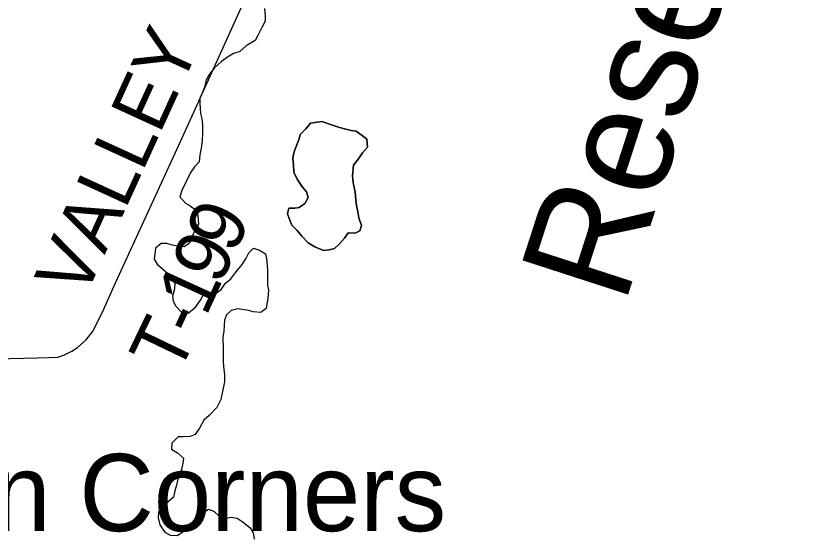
# Model space of a CAD drawing. Extents: x -10.1 to 68, y -9.5 to 29.2.
# Drawn here: x 5.518 to 6.333, y 19.418 to 19.95 of the extents above; entities that cross this region are included whole.
import ezdxf

# ---------------------------------------------------------------- set-up
doc = ezdxf.new("R2010")
doc.units = 0
for name, color, linetype in [('GM_X_Major_Lake', 7, 'Continuous'), ('GM_X_Major_Lake_Text', 7, 'Continuous'), ('GM_X_Major_River', 7, 'Continuous'), ('GM_X_Township_Road', 7, 'Continuous'), ('GM_X_Township_Road_Text', 7, 'Continuous'), ('GM_X_Unincorporated_Text', 7, 'Continuous')]:
    doc.layers.add(name, color=color, linetype=linetype)

msp = doc.modelspace()

# ---------------------------------------------------------------- linework, layer by layer
at = {"layer": 'GM_X_Major_Lake'}
for points in [[(5.77192, 19.95774), (5.77267, 19.94976), (5.77267, 19.94482), (5.76926, 19.93836), (5.76508, 19.93), (5.76242, 19.92505), (5.75331, 19.91935), (5.74686, 19.91364), (5.74041, 19.91173), (5.73434, 19.90793), (5.72789, 19.90336), (5.72068, 19.89652), (5.71574, 19.89043), (5.71233, 19.88473), (5.71081, 19.87827), (5.70853, 19.87181), (5.70588, 19.86611), (5.70588, 19.86041), (5.70663, 19.85015), (5.70777, 19.84484), (5.70852, 19.83838), (5.70852, 19.8304), (5.70814, 19.82242), (5.70738, 19.81483), (5.70586, 19.80799), (5.7051, 19.80077), (5.70055, 19.79583), (5.69599, 19.78936), (5.6922, 19.78138), (5.68726, 19.7715), (5.68536, 19.76504), (5.69105, 19.75858), (5.69598, 19.75593), (5.70092, 19.75214), (5.70395, 19.74606), (5.70432, 19.73695), (5.70091, 19.73124), (5.69863, 19.7263), (5.69521, 19.71756), (5.6899, 19.71376), (5.68459, 19.71413), (5.67776, 19.71564), (5.67207, 19.71715), (5.66638, 19.71715), (5.66031, 19.71258), (5.65917, 19.70119), (5.6622, 19.69625), (5.66751, 19.69132), (5.6732, 19.68676), (5.67813, 19.68145), (5.68041, 19.67652), (5.68003, 19.67082), (5.67775, 19.6636), (5.67851, 19.65828), (5.68116, 19.65334), (5.68685, 19.64727), (5.69406, 19.64614), (5.70165, 19.65261), (5.70734, 19.66021), (5.71114, 19.66819), (5.71645, 19.66744), (5.7229, 19.66669), (5.72783, 19.67011), (5.73201, 19.67658), (5.7377, 19.68114), (5.74263, 19.68799), (5.74909, 19.69597), (5.75288, 19.70167), (5.75592, 19.70776), (5.76085, 19.7127), (5.76692, 19.71043), (5.77299, 19.70663), (5.77413, 19.7017), (5.77489, 19.69524), (5.77526, 19.68954), (5.77526, 19.67473), (5.77602, 19.66979), (5.77564, 19.66067), (5.7745, 19.65573), (5.77374, 19.65079), (5.76842, 19.64661), (5.76046, 19.64736), (5.75552, 19.64887), (5.7449, 19.65038), (5.73807, 19.64885), (5.73314, 19.64429), (5.73124, 19.63897), (5.73086, 19.63327), (5.73048, 19.62719), (5.72934, 19.62225), (5.72971, 19.60933), (5.72971, 19.5968), (5.73009, 19.59148), (5.73123, 19.58312), (5.73122, 19.57591), (5.72895, 19.56603), (5.72743, 19.55767), (5.72325, 19.54969), (5.71528, 19.54132), (5.70997, 19.53676), (5.70541, 19.52839)], [(5.79691, 19.75339), (5.79577, 19.74769), (5.79728, 19.74275), (5.79994, 19.73592), (5.80563, 19.73061), (5.81018, 19.72491), (5.81663, 19.71808), (5.82345, 19.71391), (5.83256, 19.71012), (5.83825, 19.71089), (5.84356, 19.71204), (5.8485, 19.7166), (5.85381, 19.72269), (5.85761, 19.72839), (5.86481, 19.72801), (5.86975, 19.7303), (5.87127, 19.73562), (5.86861, 19.7436), (5.86748, 19.74967), (5.86634, 19.75613), (5.86558, 19.76183), (5.86482, 19.7698), (5.86293, 19.77968), (5.86217, 19.78651), (5.86331, 19.79753), (5.86825, 19.804), (5.87242, 19.81008), (5.87736, 19.81578), (5.87698, 19.82414), (5.87205, 19.82793), (5.86598, 19.83211), (5.86067, 19.83286), (5.85536, 19.83437), (5.84891, 19.83588), (5.84359, 19.83778), (5.83752, 19.83967), (5.83108, 19.84194), (5.82614, 19.84156), (5.81931, 19.84041), (5.81438, 19.8347), (5.80907, 19.829), (5.80679, 19.82254), (5.80375, 19.81494), (5.80223, 19.81), (5.80109, 19.8043), (5.80185, 19.79784), (5.80223, 19.79024), (5.80564, 19.78303), (5.81095, 19.77506), (5.81512, 19.77012), (5.81664, 19.76443), (5.81322, 19.75835), (5.80753, 19.75416), (5.80298, 19.7534)], [(5.80298, 19.7534), (5.79691, 19.75339)], [(5.70541, 19.52839), (5.70124, 19.52193), (5.69592, 19.52002), (5.68872, 19.51964), (5.68378, 19.51963), (5.67733, 19.51316), (5.67695, 19.50708), (5.68302, 19.50329), (5.68909, 19.4976), (5.68833, 19.49266), (5.68719, 19.4862), (5.68415, 19.47974), (5.68187, 19.47024), (5.68035, 19.46416), (5.67884, 19.4577), (5.67352, 19.45314), (5.66707, 19.44743), (5.66366, 19.44249), (5.66327, 19.43679), (5.66479, 19.42958), (5.6701, 19.42198), (5.67541, 19.41895), (5.68262, 19.41858), (5.69059, 19.42391), (5.69932, 19.43265), (5.70577, 19.4376), (5.70994, 19.44254), (5.71488, 19.44559), (5.72057, 19.44332), (5.7255, 19.43838), (5.73157, 19.43611), (5.73802, 19.43726), (5.74409, 19.4365), (5.75016, 19.43233), (5.75737, 19.42664), (5.7604, 19.42133), (5.76154, 19.41487)]]:
    msp.add_lwpolyline(points, dxfattribs=at)
at = {"layer": 'GM_X_Major_River'}
for points in [[(5.77192, 19.95774), (5.77267, 19.94976), (5.77267, 19.94482), (5.76926, 19.93836), (5.76508, 19.93), (5.76242, 19.92505), (5.75331, 19.91935), (5.74686, 19.91364), (5.74041, 19.91173), (5.73434, 19.90793), (5.72789, 19.90336), (5.72068, 19.89652), (5.71574, 19.89043), (5.71233, 19.88473), (5.71081, 19.87827), (5.70853, 19.87181), (5.70588, 19.86611), (5.70588, 19.86041), (5.70663, 19.85015), (5.70777, 19.84484), (5.70852, 19.83838), (5.70852, 19.8304), (5.70814, 19.82242), (5.70738, 19.81483), (5.70586, 19.80799), (5.7051, 19.80077), (5.70055, 19.79583), (5.69599, 19.78936), (5.6922, 19.78138), (5.68726, 19.7715), (5.68536, 19.76504), (5.69105, 19.75858), (5.69598, 19.75593), (5.70092, 19.75214), (5.70395, 19.74606), (5.70432, 19.73695), (5.70091, 19.73124), (5.69863, 19.7263), (5.69521, 19.71756), (5.6899, 19.71376), (5.68459, 19.71413), (5.67776, 19.71564), (5.67207, 19.71715), (5.66638, 19.71715), (5.66031, 19.71258), (5.65917, 19.70119), (5.6622, 19.69625), (5.66751, 19.69132), (5.6732, 19.68676), (5.67813, 19.68145), (5.68041, 19.67652), (5.68003, 19.67082), (5.67775, 19.6636), (5.67851, 19.65828), (5.68116, 19.65334), (5.68685, 19.64727), (5.69406, 19.64614), (5.70165, 19.65261), (5.70734, 19.66021), (5.71114, 19.66819), (5.71645, 19.66744), (5.7229, 19.66669), (5.72783, 19.67011), (5.73201, 19.67658), (5.7377, 19.68114), (5.74263, 19.68799), (5.74909, 19.69597), (5.75288, 19.70167), (5.75592, 19.70776), (5.76085, 19.7127), (5.76692, 19.71043), (5.77299, 19.70663), (5.77413, 19.7017), (5.77489, 19.69524), (5.77526, 19.68954), (5.77526, 19.67473), (5.77602, 19.66979), (5.77564, 19.66067), (5.7745, 19.65573), (5.77374, 19.65079), (5.76842, 19.64661), (5.76046, 19.64736), (5.75552, 19.64887), (5.7449, 19.65038), (5.73807, 19.64885), (5.73314, 19.64429), (5.73124, 19.63897), (5.73086, 19.63327), (5.73048, 19.62719), (5.72934, 19.62225), (5.72971, 19.60933), (5.72971, 19.5968), (5.73009, 19.59148), (5.73123, 19.58312), (5.73122, 19.57591), (5.72895, 19.56603), (5.72743, 19.55767), (5.72325, 19.54969), (5.71528, 19.54132), (5.70997, 19.53676), (5.70541, 19.52839)], [(5.80298, 19.7534), (5.80753, 19.75416), (5.81322, 19.75835), (5.81664, 19.76443), (5.81512, 19.77012), (5.81095, 19.77506), (5.80564, 19.78303), (5.80223, 19.79024), (5.80185, 19.79784), (5.80109, 19.8043), (5.80223, 19.81), (5.80375, 19.81494), (5.80679, 19.82254), (5.80907, 19.829), (5.81438, 19.8347), (5.81931, 19.84041), (5.82614, 19.84156), (5.83108, 19.84194), (5.83752, 19.83967), (5.84359, 19.83778), (5.84891, 19.83588), (5.85536, 19.83437), (5.86067, 19.83286), (5.86598, 19.83211), (5.87205, 19.82793), (5.87698, 19.82414), (5.87736, 19.81578), (5.87242, 19.81008), (5.86825, 19.804), (5.86331, 19.79753), (5.86217, 19.78651), (5.86293, 19.77968), (5.86482, 19.7698), (5.86558, 19.76183), (5.86634, 19.75613), (5.86748, 19.74967), (5.86861, 19.7436), (5.87127, 19.73562), (5.86975, 19.7303), (5.86481, 19.72801), (5.85761, 19.72839), (5.85381, 19.72269), (5.8485, 19.7166), (5.84356, 19.71204), (5.83825, 19.71089), (5.83256, 19.71012), (5.82345, 19.71391), (5.81663, 19.71808), (5.81018, 19.72491), (5.80563, 19.73061), (5.79994, 19.73592), (5.79728, 19.74275), (5.79577, 19.74769), (5.79691, 19.75339)], [(5.79691, 19.75339), (5.80298, 19.7534)], [(5.70541, 19.52839), (5.70124, 19.52193), (5.69592, 19.52002), (5.68872, 19.51964), (5.68378, 19.51963), (5.67733, 19.51316), (5.67695, 19.50708), (5.68302, 19.50329), (5.68909, 19.4976), (5.68833, 19.49266), (5.68719, 19.4862), (5.68415, 19.47974), (5.68187, 19.47024), (5.68035, 19.46416), (5.67884, 19.4577), (5.67352, 19.45314), (5.66707, 19.44743), (5.66366, 19.44249), (5.66327, 19.43679), (5.66479, 19.42958), (5.6701, 19.42198), (5.67541, 19.41895), (5.68262, 19.41858), (5.69059, 19.42391), (5.69932, 19.43265), (5.70577, 19.4376), (5.70994, 19.44254), (5.71488, 19.44559), (5.72057, 19.44332), (5.7255, 19.43838), (5.73157, 19.43611), (5.73802, 19.43726), (5.74409, 19.4365), (5.75016, 19.43233), (5.75737, 19.42664), (5.7604, 19.42133), (5.76154, 19.41487)]]:
    msp.add_lwpolyline(points, dxfattribs=at)
at = {"layer": 'GM_X_Township_Road'}
for points in [[(5.57474, 19.6073), (5.58065, 19.61108), (5.58964, 19.61864), (5.59673, 19.6281), (5.60737, 19.64962), (5.61966, 19.67705), (5.68421, 19.81797), (5.72488, 19.90711), (5.77264, 20.0128)], [(5.17331, 19.59552), (5.21768, 19.5965), (5.3104, 19.59736), (5.38438, 19.59822), (5.45108, 19.59902), (5.49701, 19.59936), (5.53927, 19.60044), (5.55094, 19.60056), (5.56055, 19.60115), (5.5667, 19.60304), (5.57474, 19.6073)]]:
    msp.add_lwpolyline(points, dxfattribs=at)

# ---------------------------------------------------------------- texts
at = {"layer": 'GM_X_Major_Lake_Text'}
msp.add_text('Reservoir', height=0.11372, rotation=72.06558, dxfattribs=at).set_placement((6.14055, 19.65318))
at = {"layer": 'GM_X_Township_Road_Text'}
for s, height, rotation, p in [('VALLEY', 0.056818, 65.42844, (5.58722, 19.6591)), ('9', 0.05682, 65.53256, (5.74113, 19.70524)), ('9', 0.05682, 65.50692, (5.72661, 19.67337)), ('1', 0.05682, 65.41175, (5.712, 19.64144)), ('T', 0.05682, 64.37413, (5.68336, 19.58093)), ('-', 0.05682, 65.21072, (5.70213, 19.62006))]:
    msp.add_text(s, height=height, rotation=rotation, dxfattribs=at).set_placement(p)
at = {"layer": 'GM_X_Unincorporated_Text'}
msp.add_text('Auburn Corners', height=0.0789773, rotation=0.00001, dxfattribs=at).set_placement((5.21255, 19.4231))

doc.saveas('drawing.dxf')
